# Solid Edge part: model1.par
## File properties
Author: Deepak Maini
Template: normal.par
Last saved by: Robert a Rhodes jr
Revision: 5
Application: Solid Edge
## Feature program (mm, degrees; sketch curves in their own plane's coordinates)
sketch for "unnamed Protrusion 1" plane through (0, 0, 0) normal (0, -1, 0) x-axis (1, 0, 0)
  arc centre (60, 0) radius 30 from (60, 30) to (60, -30) cw
  line (104, -30) -> (60, -30)
  line (104, 18) -> (104, -30)
  line (164, 18) -> (104, 18)
  line (164, -4) -> (164, 18)
  line (182, -4) -> (164, -4)
  line (182, -4) -> (182, 36)
  line (142, 36) -> (182, 36)
  line (142, 30) -> (142, 36)
  line (60, 30) -> (142, 30)
extrude "unnamed Protrusion 1" add finite 54 symmetric
sketch for "unnamed Protrusion 2" #1 plane through (0, 0, 0) normal (0, -1, 0) x-axis (1, 0, 0)
  arc centre (60, 0) radius 30 from (60, 30) to (60, -30) ccw
  arc centre (60, 0) radius 30 from (60, 30) to (60, -30) cw
sketch for "unnamed Protrusion 2" #2 plane through (0, 0, 0) normal (0, -1, 0) x-axis (1, 0, 0)
  circle centre (60, 0) radius 18
extrude "unnamed Protrusion 2" add finite 66 symmetric
sketch for "unnamed Protrusion 3" plane through (0, 0, 0) normal (0, -1, 0) x-axis (1, 0, 0)
  line (104, -30) -> (164, -4)
  line (164, -4) -> (164, 18)
  line (164, 18) -> (104, 18)
  line (104, 18) -> (104, -30)
extrude "unnamed Protrusion 3" add finite 18 symmetric
sketch for "unnamed Protrusion 4" plane through (0, 0, 0) normal (0, -1, 0) x-axis (1, 0, 0)
  line (200, 76) -> (200, -4)
  line (200, -4) -> (182, -4)
  line (182, -4) -> (182, 36)
  line (182, 76) -> (182, 36)
  line (182, 76) -> (200, 76)
extrude "unnamed Protrusion 4" add finite 92 symmetric
sketch for "unnamed Protrusion 5" plane through (0, 0, 0) normal (0, -1, 0) x-axis (1, 0, 0)
  line (142, 36) -> (182, 76)
  line (182, 76) -> (182, 36)
  line (142, 36) -> (182, 36)
extrude "unnamed Protrusion 5" add finite 12 symmetric
sketch for "unnamed Hole 1" plane through (200, 0, 36) normal (1, 0, 0) x-axis (0, 1, 0)
hole "unnamed Hole 1" through
sketch for "unnamed Hole 2" plane through (200, 0, 36) normal (1, 0, 0) x-axis (0, 1, 0)
  hole centre (-30, 22) bore radius 8
hole "unnamed Hole 2" through
pattern "unnamed Pattern 1" of "unnamed Hole 1", "unnamed Hole 2"
fillet "unnamed Round 1"
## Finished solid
Body 1: solid body, 34 faces, 81 edges, 46 vertices.
  Faces by surface: plane 28, cylinder 6
  Edges by curve: line 67, circle 14
Bounding box of the edges (mm): 170.000 x 92.000 x 106.000, from (30, -46, -30) to (200, 46, 76).
Cylindrical faces by radius (mm): R8 x2, R16 x2, R18 x1, R30 x1
Planar faces by outward normal: +x 3, +y 5, +z 4, -x 5, -y 5, -z 4, oblique 2
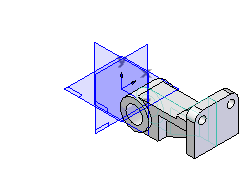
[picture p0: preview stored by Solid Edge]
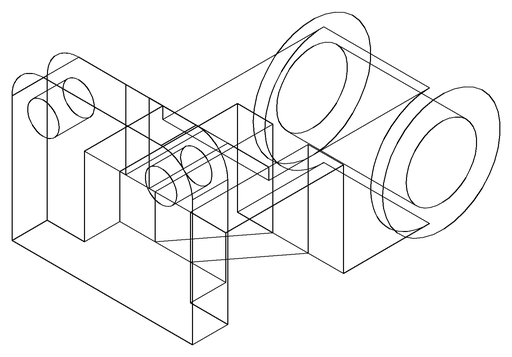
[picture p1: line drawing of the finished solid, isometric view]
